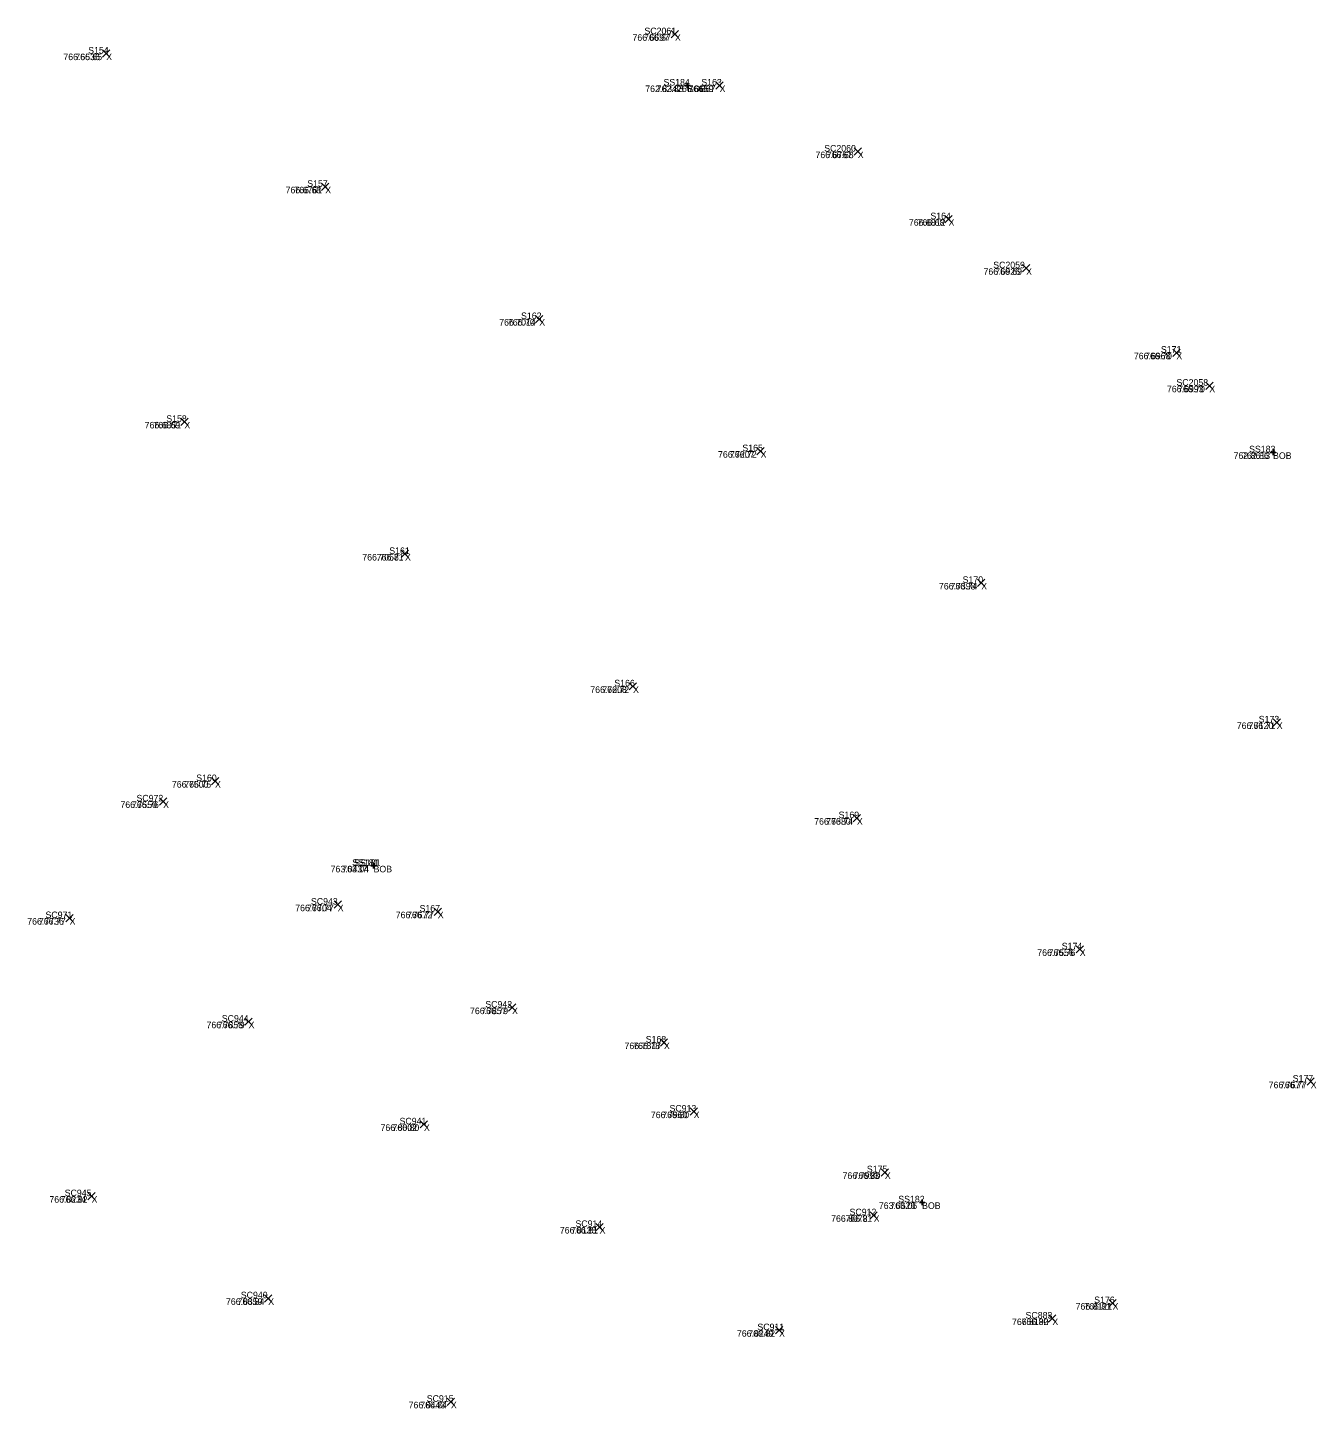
# Model space of a CAD drawing. Extents: x 1845019 to 1877956, y 680444 to 701081.
# Drawn here: x 1857591.25 to 1857603.05, y 694328.94 to 694341.58 of the extents above; entities that cross this region are included whole.
import ezdxf

# ---------------------------------------------------------------- set-up
doc = ezdxf.new("R2010")
doc.units = 0
for name, color, linetype in [('BR_X_SV_Bottom_of_Beam_Text', 7, 'Continuous'), ('SV_X_Random_Point', 7, 'Continuous'), ('SV_X_Text_Comment', 7, 'Continuous'), ('SV_X_Text_Elevation', 7, 'Continuous'), ('SV_X_Text_Name', 7, 'Continuous')]:
    doc.layers.add(name, color=color, linetype=linetype)

msp = doc.modelspace()

# ---------------------------------------------------------------- linework, layer by layer
at = {"layer": 'BR_X_SV_Bottom_of_Beam_Text'}
for p, q in [((1857597.289, 694341.074), (1857597.289, 694341.024)), ((1857597.289, 694341.074), (1857597.289, 694341.024)), ((1857597.264, 694341.049), (1857597.314, 694341.049)), ((1857597.264, 694341.049), (1857597.314, 694341.049)), ((1857597.289, 694341.049), (1857597.289, 694341.049)), ((1857597.289, 694341.049), (1857597.289, 694341.049)), ((1857602.625, 694337.691), (1857602.675, 694337.691)), ((1857602.625, 694337.691), (1857602.675, 694337.691)), ((1857602.65, 694337.716), (1857602.65, 694337.666)), ((1857602.65, 694337.716), (1857602.65, 694337.666)), ((1857602.65, 694337.691), (1857602.65, 694337.691)), ((1857602.65, 694337.691), (1857602.65, 694337.691)), ((1857594.392, 694333.907), (1857594.442, 694333.907)), ((1857594.392, 694333.907), (1857594.442, 694333.907)), ((1857594.417, 694333.932), (1857594.417, 694333.882)), ((1857594.417, 694333.932), (1857594.417, 694333.882)), ((1857594.417, 694333.907), (1857594.417, 694333.907)), ((1857594.417, 694333.907), (1857594.417, 694333.907)), ((1857599.413, 694330.826), (1857599.463, 694330.826)), ((1857599.413, 694330.826), (1857599.463, 694330.826)), ((1857599.438, 694330.851), (1857599.438, 694330.801)), ((1857599.438, 694330.851), (1857599.438, 694330.801)), ((1857599.438, 694330.826), (1857599.438, 694330.826)), ((1857599.438, 694330.826), (1857599.438, 694330.826))]:
    msp.add_line(p, q, dxfattribs=at)
at = {"layer": 'SV_X_Random_Point'}
for p, q in [((1857597.142, 694341.484), (1857597.209, 694341.551)), ((1857597.142, 694341.551), (1857597.209, 694341.484)), ((1857597.142, 694341.484), (1857597.209, 694341.551)), ((1857597.142, 694341.551), (1857597.209, 694341.484)), ((1857591.937, 694341.308), (1857592.003, 694341.375)), ((1857591.937, 694341.375), (1857592.003, 694341.308)), ((1857591.937, 694341.308), (1857592.003, 694341.375)), ((1857591.937, 694341.375), (1857592.003, 694341.308)), ((1857597.55, 694341.016), (1857597.617, 694341.082)), ((1857597.55, 694341.082), (1857597.617, 694341.016)), ((1857597.55, 694341.016), (1857597.617, 694341.082)), ((1857597.55, 694341.082), (1857597.617, 694341.016)), ((1857598.816, 694340.41), (1857598.882, 694340.477)), ((1857598.816, 694340.477), (1857598.882, 694340.41)), ((1857598.816, 694340.41), (1857598.882, 694340.477)), ((1857598.816, 694340.477), (1857598.882, 694340.41)), ((1857593.942, 694340.089), (1857594.009, 694340.155)), ((1857593.942, 694340.155), (1857594.009, 694340.089)), ((1857593.942, 694340.089), (1857594.009, 694340.155)), ((1857593.942, 694340.155), (1857594.009, 694340.089)), ((1857599.647, 694339.791), (1857599.713, 694339.858)), ((1857599.647, 694339.858), (1857599.713, 694339.791)), ((1857599.647, 694339.791), (1857599.713, 694339.858)), ((1857599.647, 694339.858), (1857599.713, 694339.791)), ((1857600.357, 694339.342), (1857600.424, 694339.409)), ((1857600.357, 694339.409), (1857600.424, 694339.342)), ((1857600.357, 694339.342), (1857600.424, 694339.409)), ((1857600.357, 694339.409), (1857600.424, 694339.342)), ((1857595.9, 694338.878), (1857595.967, 694338.945)), ((1857595.9, 694338.945), (1857595.967, 694338.878)), ((1857595.9, 694338.878), (1857595.967, 694338.945)), ((1857595.9, 694338.945), (1857595.967, 694338.878)), ((1857601.732, 694338.569), (1857601.799, 694338.636)), ((1857601.732, 694338.636), (1857601.799, 694338.569)), ((1857601.732, 694338.569), (1857601.799, 694338.636)), ((1857601.732, 694338.636), (1857601.799, 694338.569)), ((1857602.034, 694338.267), (1857602.101, 694338.334)), ((1857602.034, 694338.334), (1857602.101, 694338.267)), ((1857602.034, 694338.267), (1857602.101, 694338.334)), ((1857602.034, 694338.334), (1857602.101, 694338.267)), ((1857592.652, 694337.937), (1857592.719, 694338.003)), ((1857592.652, 694338.003), (1857592.719, 694337.937)), ((1857592.652, 694337.937), (1857592.719, 694338.003)), ((1857592.652, 694338.003), (1857592.719, 694337.937)), ((1857597.926, 694337.668), (1857597.993, 694337.735)), ((1857597.926, 694337.735), (1857597.993, 694337.668)), ((1857597.926, 694337.668), (1857597.993, 694337.735)), ((1857597.926, 694337.735), (1857597.993, 694337.668)), ((1857594.671, 694336.728), (1857594.738, 694336.795)), ((1857594.671, 694336.795), (1857594.738, 694336.728)), ((1857594.671, 694336.728), (1857594.738, 694336.795)), ((1857594.671, 694336.795), (1857594.738, 694336.728)), ((1857599.946, 694336.463), (1857600.012, 694336.53)), ((1857599.946, 694336.53), (1857600.012, 694336.463)), ((1857599.946, 694336.463), (1857600.012, 694336.53)), ((1857599.946, 694336.53), (1857600.012, 694336.463)), ((1857596.758, 694335.516), (1857596.825, 694335.582)), ((1857596.758, 694335.582), (1857596.825, 694335.516)), ((1857596.758, 694335.516), (1857596.825, 694335.582)), ((1857596.758, 694335.582), (1857596.825, 694335.516)), ((1857602.651, 694335.186), (1857602.717, 694335.252)), ((1857602.651, 694335.252), (1857602.717, 694335.186)), ((1857602.651, 694335.186), (1857602.717, 694335.252)), ((1857602.651, 694335.252), (1857602.717, 694335.186)), ((1857592.933, 694334.648), (1857593, 694334.715)), ((1857592.933, 694334.715), (1857593, 694334.648)), ((1857592.933, 694334.648), (1857593, 694334.715)), ((1857592.933, 694334.715), (1857593, 694334.648)), ((1857592.457, 694334.463), (1857592.524, 694334.53)), ((1857592.457, 694334.53), (1857592.524, 694334.463)), ((1857592.457, 694334.463), (1857592.524, 694334.53)), ((1857592.457, 694334.53), (1857592.524, 694334.463)), ((1857598.808, 694334.31), (1857598.874, 694334.377)), ((1857598.808, 694334.377), (1857598.874, 694334.31)), ((1857598.808, 694334.31), (1857598.874, 694334.377)), ((1857598.808, 694334.377), (1857598.874, 694334.31)), ((1857594.056, 694333.518), (1857594.123, 694333.585)), ((1857594.056, 694333.585), (1857594.123, 694333.518)), ((1857594.056, 694333.518), (1857594.123, 694333.585)), ((1857594.056, 694333.585), (1857594.123, 694333.518)), ((1857594.971, 694333.453), (1857595.038, 694333.52)), ((1857594.971, 694333.52), (1857595.038, 694333.453)), ((1857594.971, 694333.453), (1857595.038, 694333.52)), ((1857594.971, 694333.52), (1857595.038, 694333.453)), ((1857591.602, 694333.394), (1857591.669, 694333.461)), ((1857591.602, 694333.461), (1857591.669, 694333.394)), ((1857591.602, 694333.394), (1857591.669, 694333.461)), ((1857591.602, 694333.461), (1857591.669, 694333.394)), ((1857600.847, 694333.109), (1857600.914, 694333.175)), ((1857600.847, 694333.175), (1857600.914, 694333.109)), ((1857600.847, 694333.109), (1857600.914, 694333.175)), ((1857600.847, 694333.175), (1857600.914, 694333.109)), ((1857595.652, 694332.575), (1857595.718, 694332.642)), ((1857595.652, 694332.642), (1857595.718, 694332.575)), ((1857595.652, 694332.575), (1857595.718, 694332.642)), ((1857595.652, 694332.642), (1857595.718, 694332.575)), ((1857593.24, 694332.447), (1857593.307, 694332.513)), ((1857593.24, 694332.513), (1857593.307, 694332.447)), ((1857593.24, 694332.447), (1857593.307, 694332.513)), ((1857593.24, 694332.513), (1857593.307, 694332.447)), ((1857597.042, 694332.255), (1857597.108, 694332.322)), ((1857597.042, 694332.322), (1857597.108, 694332.255)), ((1857597.042, 694332.255), (1857597.108, 694332.322)), ((1857597.042, 694332.322), (1857597.108, 694332.255)), ((1857602.962, 694331.898), (1857603.028, 694331.965)), ((1857602.962, 694331.965), (1857603.028, 694331.898)), ((1857602.962, 694331.898), (1857603.028, 694331.965)), ((1857602.962, 694331.965), (1857603.028, 694331.898)), ((1857597.314, 694331.623), (1857597.381, 694331.69)), ((1857597.314, 694331.69), (1857597.381, 694331.623)), ((1857597.314, 694331.623), (1857597.381, 694331.69)), ((1857597.314, 694331.69), (1857597.381, 694331.623)), ((1857594.844, 694331.507), (1857594.911, 694331.573)), ((1857594.844, 694331.573), (1857594.911, 694331.507)), ((1857594.844, 694331.507), (1857594.911, 694331.573)), ((1857594.844, 694331.573), (1857594.911, 694331.507)), ((1857599.063, 694331.067), (1857599.13, 694331.134)), ((1857599.063, 694331.134), (1857599.13, 694331.067)), ((1857599.063, 694331.067), (1857599.13, 694331.134)), ((1857599.063, 694331.134), (1857599.13, 694331.067)), ((1857591.802, 694330.85), (1857591.869, 694330.917)), ((1857591.802, 694330.917), (1857591.869, 694330.85)), ((1857591.802, 694330.85), (1857591.869, 694330.917)), ((1857591.802, 694330.917), (1857591.869, 694330.85)), ((1857598.962, 694330.675), (1857599.028, 694330.741)), ((1857598.962, 694330.741), (1857599.028, 694330.675)), ((1857598.962, 694330.675), (1857599.028, 694330.741)), ((1857598.962, 694330.741), (1857599.028, 694330.675)), ((1857596.452, 694330.567), (1857596.519, 694330.634)), ((1857596.452, 694330.634), (1857596.519, 694330.567)), ((1857596.452, 694330.567), (1857596.519, 694330.634)), ((1857596.452, 694330.634), (1857596.519, 694330.567)), ((1857593.42, 694329.914), (1857593.486, 694329.981)), ((1857593.42, 694329.981), (1857593.486, 694329.914)), ((1857593.42, 694329.914), (1857593.486, 694329.981)), ((1857593.42, 694329.981), (1857593.486, 694329.914)), ((1857601.148, 694329.87), (1857601.215, 694329.937)), ((1857601.148, 694329.937), (1857601.215, 694329.87)), ((1857601.148, 694329.87), (1857601.215, 694329.937)), ((1857601.148, 694329.937), (1857601.215, 694329.87)), ((1857598.096, 694329.623), (1857598.162, 694329.69)), ((1857598.096, 694329.69), (1857598.162, 694329.623)), ((1857598.096, 694329.623), (1857598.162, 694329.69)), ((1857598.096, 694329.69), (1857598.162, 694329.623)), ((1857600.596, 694329.729), (1857600.663, 694329.796)), ((1857600.596, 694329.796), (1857600.663, 694329.729)), ((1857600.596, 694329.729), (1857600.663, 694329.796)), ((1857600.596, 694329.796), (1857600.663, 694329.729)), ((1857595.092, 694328.968), (1857595.159, 694329.035)), ((1857595.092, 694329.035), (1857595.159, 694328.968)), ((1857595.092, 694328.968), (1857595.159, 694329.035)), ((1857595.092, 694329.035), (1857595.159, 694328.968))]:
    msp.add_line(p, q, dxfattribs=at)

# ---------------------------------------------------------------- texts
at = {"layer": 'BR_X_SV_Bottom_of_Beam_Text'}
for s, p in [('SS184', (1857597.071, 694341.049)), ('SS184', (1857597.071, 694341.049)), ('762.8342', (1857596.904, 694340.989)), ('762.83', (1857597.009, 694340.989)), ('BOB', (1857597.289, 694340.989)), ('762.8613', (1857602.289, 694337.631)), ('762.86', (1857602.366, 694337.631)), ('SS183', (1857602.431, 694337.691)), ('SS183', (1857602.431, 694337.691)), ('BOB', (1857602.65, 694337.631)), ('763.0437', (1857594.024, 694333.847)), ('763.04', (1857594.13, 694333.847)), ('SS181', (1857594.221, 694333.907)), ('SS181', (1857594.239, 694333.907)), ('BOB', (1857594.417, 694333.847)), ('763.0620', (1857599.042, 694330.766)), ('763.06', (1857599.147, 694330.766)), ('SS182', (1857599.22, 694330.826)), ('SS182', (1857599.22, 694330.826)), ('BOB', (1857599.438, 694330.766))]:
    msp.add_text(s, height=0.06, dxfattribs=at).set_placement(p)
at = {"layer": 'SV_X_Text_Comment'}
for p in [(1857597.176, 694341.458), (1857591.97, 694341.281), (1857597.584, 694340.989), (1857598.849, 694340.384), (1857593.975, 694340.062), (1857599.68, 694339.765), (1857600.39, 694339.316), (1857595.934, 694338.851), (1857601.765, 694338.543), (1857602.067, 694338.241), (1857592.686, 694337.91), (1857597.96, 694337.642), (1857594.705, 694336.701), (1857599.979, 694336.436), (1857596.792, 694335.489), (1857602.684, 694335.159), (1857592.966, 694334.622), (1857592.491, 694334.436), (1857598.841, 694334.283), (1857594.089, 694333.491), (1857595.005, 694333.427), (1857591.635, 694333.368), (1857600.881, 694333.082), (1857595.685, 694332.549), (1857593.273, 694332.42), (1857597.075, 694332.229), (1857602.995, 694331.871), (1857597.347, 694331.597), (1857594.878, 694331.48), (1857599.097, 694331.041), (1857591.836, 694330.823), (1857598.995, 694330.648), (1857596.486, 694330.541), (1857593.453, 694329.888), (1857601.181, 694329.844), (1857600.63, 694329.703), (1857598.129, 694329.596), (1857595.125, 694328.941)]:
    msp.add_text('X', height=0.06, dxfattribs=at).set_placement(p)
at = {"layer": 'SV_X_Text_Elevation'}
for s, p in [('766.6697', (1857596.787, 694341.458)), ('766.67', (1857596.893, 694341.458)), ('766.6536', (1857591.578, 694341.281)), ('766.65', (1857591.687, 694341.281)), ('766.6659', (1857597.195, 694340.989)), ('766.67', (1857597.301, 694340.989)), ('766.6767', (1857598.462, 694340.384)), ('766.68', (1857598.566, 694340.384)), ('766.6761', (1857593.612, 694340.062)), ('766.68', (1857593.692, 694340.062)), ('766.6812', (1857599.317, 694339.765)), ('766.68', (1857599.396, 694339.765)), ('766.6926', (1857600, 694339.316)), ('766.69', (1857600.107, 694339.316)), ('766.7014', (1857595.567, 694338.851)), ('766.70', (1857595.647, 694338.851)), ('766.6968', (1857601.376, 694338.543)), ('766.70', (1857601.479, 694338.543)), ('766.6993', (1857601.679, 694338.241)), ('766.70', (1857601.781, 694338.241)), ('766.6851', (1857592.322, 694337.91)), ('766.69', (1857592.402, 694337.91)), ('766.7207', (1857597.57, 694337.642)), ('766.72', (1857597.679, 694337.642)), ('766.7058', (1857594.314, 694336.701)), ('766.71', (1857594.446, 694336.701)), ('766.7398', (1857599.592, 694336.436)), ('766.74', (1857599.698, 694336.436)), ('766.7208', (1857596.401, 694335.489)), ('766.72', (1857596.511, 694335.489)), ('766.7120', (1857602.318, 694335.159)), ('766.71', (1857602.426, 694335.159)), ('766.7500', (1857592.571, 694334.622)), ('766.75', (1857592.685, 694334.622)), ('766.7550', (1857592.1, 694334.436)), ('766.76', (1857592.206, 694334.436)), ('766.7380', (1857598.45, 694334.283)), ('766.74', (1857598.56, 694334.283)), ('766.7704', (1857593.7, 694333.491)), ('766.77', (1857593.808, 694333.491)), ('766.7672', (1857594.62, 694333.427)), ('766.77', (1857594.724, 694333.427)), ('766.7736', (1857591.247, 694333.368)), ('766.77', (1857591.354, 694333.368)), ('766.7556', (1857600.492, 694333.082)), ('766.76', (1857600.596, 694333.082)), ('766.7857', (1857595.3, 694332.549)), ('766.79', (1857595.403, 694332.549)), ('766.7858', (1857592.888, 694332.42)), ('766.79', (1857592.992, 694332.42)), ('766.7817', (1857596.714, 694332.229)), ('766.78', (1857596.794, 694332.229)), ('766.7677', (1857602.61, 694331.871)), ('766.77', (1857602.714, 694331.871)), ('766.7960', (1857596.955, 694331.597)), ('766.80', (1857597.06, 694331.597)), ('766.8002', (1857594.481, 694331.48)), ('766.80', (1857594.59, 694331.48)), ('766.7993', (1857598.71, 694331.041)), ('766.80', (1857598.81, 694331.041)), ('766.8234', (1857591.45, 694330.823)), ('766.82', (1857591.554, 694330.823)), ('766.8072', (1857598.605, 694330.648)), ('766.81', (1857598.736, 694330.648)), ('766.8138', (1857596.122, 694330.541)), ('766.81', (1857596.226, 694330.541)), ('766.8359', (1857593.066, 694329.888)), ('766.84', (1857593.172, 694329.888)), ('766.8121', (1857600.843, 694329.844)), ('766.81', (1857600.922, 694329.844)), ('766.8190', (1857600.261, 694329.703)), ('766.82', (1857600.348, 694329.703)), ('766.8249', (1857597.743, 694329.596)), ('766.82', (1857597.847, 694329.596)), ('766.8443', (1857594.738, 694328.941)), ('766.84', (1857594.844, 694328.941))]:
    msp.add_text(s, height=0.06, dxfattribs=at).set_placement(p)
at = {"layer": 'SV_X_Text_Name'}
for s, p in [('SC2061', (1857596.896, 694341.518)), ('SC2061', (1857596.897, 694341.518)), ('S154', (1857591.805, 694341.341)), ('S154', (1857591.805, 694341.341)), ('S163', (1857597.417, 694341.049)), ('S163', (1857597.417, 694341.049)), ('SC2060', (1857598.542, 694340.444)), ('SC2060', (1857598.542, 694340.444)), ('S157', (1857593.81, 694340.122)), ('S157', (1857593.81, 694340.122)), ('S164', (1857599.514, 694339.825)), ('S164', (1857599.514, 694339.825)), ('SC2059', (1857600.089, 694339.376)), ('SC2059', (1857600.089, 694339.376)), ('S162', (1857595.767, 694338.911)), ('S162', (1857595.767, 694338.911)), ('S171', (1857601.623, 694338.603)), ('S171', (1857601.624, 694338.603)), ('SC2058', (1857601.766, 694338.301)), ('SC2058', (1857601.766, 694338.301)), ('S158', (1857592.52, 694337.97)), ('S158', (1857592.52, 694337.97)), ('S165', (1857597.793, 694337.702)), ('S165', (1857597.793, 694337.702)), ('S161', (1857594.561, 694336.761)), ('S161', (1857594.561, 694336.761)), ('S170', (1857599.809, 694336.496)), ('S170', (1857599.809, 694336.496)), ('S166', (1857596.621, 694335.549)), ('S166', (1857596.621, 694335.549)), ('S173', (1857602.519, 694335.219)), ('S173', (1857602.519, 694335.219)), ('S160', (1857592.794, 694334.682)), ('S160', (1857592.794, 694334.682)), ('SC972', (1857592.247, 694334.496)), ('SC972', (1857592.247, 694334.496)), ('S169', (1857598.674, 694334.343)), ('S169', (1857598.674, 694334.343)), ('SC943', (1857593.844, 694333.551)), ('SC943', (1857593.844, 694333.551)), ('SC971', (1857591.414, 694333.428)), ('SC971', (1857591.415, 694333.428)), ('S167', (1857594.838, 694333.487)), ('S167', (1857594.838, 694333.487)), ('S174', (1857600.716, 694333.142)), ('S174', (1857600.716, 694333.142)), ('SC942', (1857595.44, 694332.609)), ('SC942', (1857595.44, 694332.609)), ('SC944', (1857593.028, 694332.48)), ('SC944', (1857593.028, 694332.48)), ('S168', (1857596.908, 694332.289)), ('S168', (1857596.908, 694332.289)), ('S177', (1857602.83, 694331.931)), ('S177', (1857602.83, 694331.931)), ('SC913', (1857597.126, 694331.657)), ('SC913', (1857597.126, 694331.657)), ('SC941', (1857594.655, 694331.54)), ('SC941', (1857594.655, 694331.54)), ('S175', (1857598.932, 694331.101)), ('S175', (1857598.932, 694331.101)), ('SC945', (1857591.59, 694330.883)), ('SC945', (1857591.59, 694330.883)), ('SC912', (1857598.774, 694330.708)), ('SC912', (1857598.774, 694330.708)), ('SC914', (1857596.265, 694330.601)), ('SC914', (1857596.265, 694330.601)), ('SC940', (1857593.202, 694329.948)), ('SC940', (1857593.202, 694329.948)), ('S176', (1857601.013, 694329.904)), ('S176', (1857601.013, 694329.904)), ('SC883', (1857600.385, 694329.763)), ('SC883', (1857600.385, 694329.763)), ('SC911', (1857597.931, 694329.656)), ('SC911', (1857597.93, 694329.656)), ('SC915', (1857594.904, 694329.001)), ('SC915', (1857594.904, 694329.001))]:
    msp.add_text(s, height=0.06, dxfattribs=at).set_placement(p)

doc.saveas('drawing.dxf')
